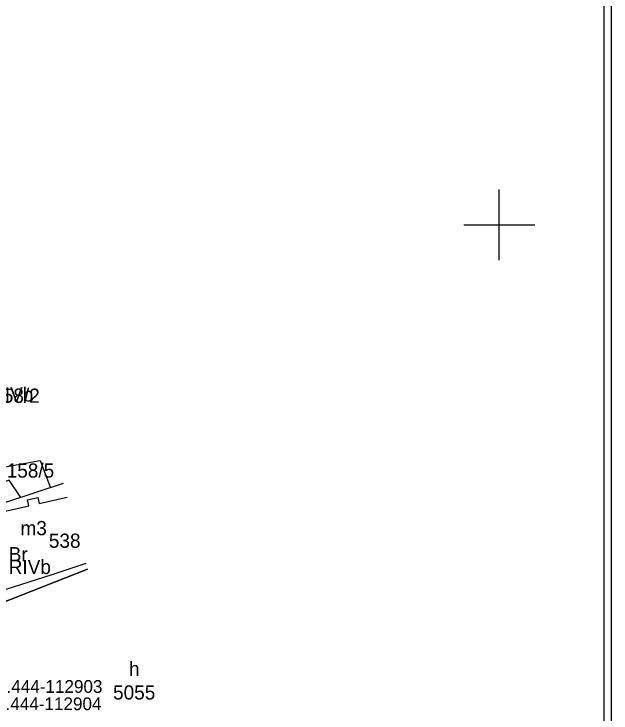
# Model space of a CAD drawing. Extents: x 6512400 to 6513200, y 6022500 to 6022750.
# Drawn here: x 6512865.8 to 6512907.88, y 6022615.57 to 6022664.87 of the extents above; entities that cross this region are included whole.
import ezdxf

# ---------------------------------------------------------------- set-up
doc = ezdxf.new("R2010")
doc.units = 0
for name, color, linetype in [('121-Punkt osnowy szczegółowej-Atr103', 7, 'Continuous'), ('209-oznaczenie konturu klasyfikacyjnego', 7, 'Continuous'), ('210-oznaczenie konturu użytku gruntowego', 7, 'Continuous'), ('211-numer działki ewidencyjnej', 7, 'Continuous'), ('217-kontur klasyfikacyjny', 7, 'Continuous'), ('218-kontur użytku gruntowego', 7, 'Continuous'), ('219-działka ewidencyjna', 7, 'Continuous'), ('312-budynek ewidencyjny', 7, 'Continuous'), ('312-oznaczenie budynku ewidencyjnego', 7, 'Continuous'), ('312-oznaczenie budynku ewidencyjnego-Atr117', 7, 'Continuous'), ('budynek projektowany (powierzchnia)', 7, 'Continuous'), ('Miejsce błędu lub ostrzeżenia po kontroli', 7, 'Continuous'), ('przewód kanalizacyjny (linia)', 7, 'Continuous'), ('przewód wodociągowy (linia)', 7, 'Continuous'), ('Wstawianie ramki sekcyjnej z opisem', 7, 'Continuous')]:
    doc.layers.add(name, color=color, linetype=linetype)

# ---------------------------------------------------------------- blocks, each defined once
blk = doc.blocks.new('RAMKA500K')
for p, q in [((100, 147.5), (100, 152.5)), ((97.5, 150), (102.5, 150))]:
    blk.add_line(p, q)

msp = doc.modelspace()

# ---------------------------------------------------------------- linework, layer by layer
at = {"layer": '217-kontur klasyfikacyjny'}
for points in [[(6512860.89, 6022621.75), (6512870.984, 6022625.716)], [(6512870.984, 6022625.716), (6512860.89, 6022621.75)]]:
    msp.add_lwpolyline(points, dxfattribs=at)
at = {"layer": '218-kontur użytku gruntowego'}
for points in [[(6512860.89, 6022621.75), (6512870.984, 6022625.716)], [(6512870.984, 6022625.716), (6512860.89, 6022621.75)]]:
    msp.add_lwpolyline(points, dxfattribs=at)
at = {"layer": '219-działka ewidencyjna'}
msp.add_lwpolyline([(6512870.984, 6022625.716), (6512860.89, 6022621.75)], dxfattribs=at)
at = {"layer": '312-budynek ewidencyjny'}
for points in [[(6512859.49, 6022628.57), (6512869.283, 6022631.773)], [(6512870.872, 6022626.113), (6512868.47, 6022625.31)], [(6512868.47, 6022625.31), (6512860.79, 6022622.86)]]:
    msp.add_lwpolyline(points, dxfattribs=at)
at = {"layer": 'budynek projektowany (powierzchnia)'}
msp.add_lwpolyline([(6512860.72, 6022623.09), (6512862.25, 6022623.44), (6512860.87, 6022629.27), (6512861.83, 6022629.49), (6512861.93, 6022629.04), (6512864.04, 6022629.53), (6512863.94, 6022629.96), (6512864.66, 6022630.15), (6512864.76, 6022629.7), (6512866.84, 6022630.17), (6512866.75, 6022630.61), (6512867.48, 6022630.77), (6512867.57, 6022630.34), (6512869.559, 6022630.79)], dxfattribs=at)
at = {"layer": 'Miejsce błędu lub ostrzeżenia po kontroli'}
for points in [[(6512620.44, 6022519.14), (6512620.44, 6022719.53), (6512907.88, 6022719.53), (6512907.88, 6022519.14)], [(6512657.26, 6022519.64), (6512657.26, 6022719.03), (6512907.38, 6022719.03), (6512907.38, 6022519.64)]]:
    msp.add_lwpolyline(points, close=True, dxfattribs=at)
at = {"layer": 'przewód kanalizacyjny (linia)'}
msp.add_lwpolyline([(6512866.28, 6022630.76), (6512865.47, 6022631.98), (6512860.85, 6022630.32)], dxfattribs=at)
at = {"layer": 'przewód wodociągowy (linia)'}
msp.add_lwpolyline([(6512853.02, 6022630.73), (6512867.64, 6022633.38), (6512868.37, 6022631.46)], dxfattribs=at)

# ---------------------------------------------------------------- block references
at = {"layer": 'Wstawianie ramki sekcyjnej z opisem'}
msp.add_blockref('RAMKA500K', (6512800, 6022500), dxfattribs=at)

# ---------------------------------------------------------------- texts
at = {"layer": '121-Punkt osnowy szczegółowej-Atr103'}
for s, p in [('314.444-112903', (6512863.27, 6022616.99)), ('314.444-112904', (6512863.2, 6022615.77))]:
    msp.add_text(s, height=0.9, dxfattribs=at).set_placement(p)
at = {"layer": '209-oznaczenie konturu klasyfikacyjnego'}
for p in [(6512864.19, 6022637.53), (6512865.43, 6022625.37)]:
    msp.add_text('RIVb', height=1, dxfattribs=at).set_placement(p)
at = {"layer": '210-oznaczenie konturu użytku gruntowego'}
msp.add_text('Br', height=1, dxfattribs=at).set_placement((6512865.43, 6022626.27))
at = {"layer": '211-numer działki ewidencyjnej'}
for s, p in [('158/2', (6512864.27, 6022637.45)), ('158/5', (6512865.29, 6022632.17))]:
    msp.add_text(s, height=1, dxfattribs=at).set_placement(p)
at = {"layer": '312-oznaczenie budynku ewidencyjnego'}
for s, p in [('538', (6512868.26, 6022627.22)), ('5055', (6512872.785, 6022616.52))]:
    msp.add_text(s, height=1, dxfattribs=at).set_placement(p)
at = {"layer": '312-oznaczenie budynku ewidencyjnego-Atr117'}
for s, p in [('m3', (6512866.26, 6022628.11)), ('h', (6512873.91, 6022618.18))]:
    msp.add_text(s, height=1, dxfattribs=at).set_placement(p)

doc.saveas('drawing.dxf')
